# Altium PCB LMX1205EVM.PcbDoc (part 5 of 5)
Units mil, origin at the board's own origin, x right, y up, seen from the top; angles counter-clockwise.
Board outline 5000 x 5000 mil, 6 copper layers (Top Layer, RF GND, Signal Layer 3, Signal Layer 4, Signal Layer 5, Bottom Layer), stack 61.6 mil thick; 176 components, 99 nets, 572 pads, 2473 vias.
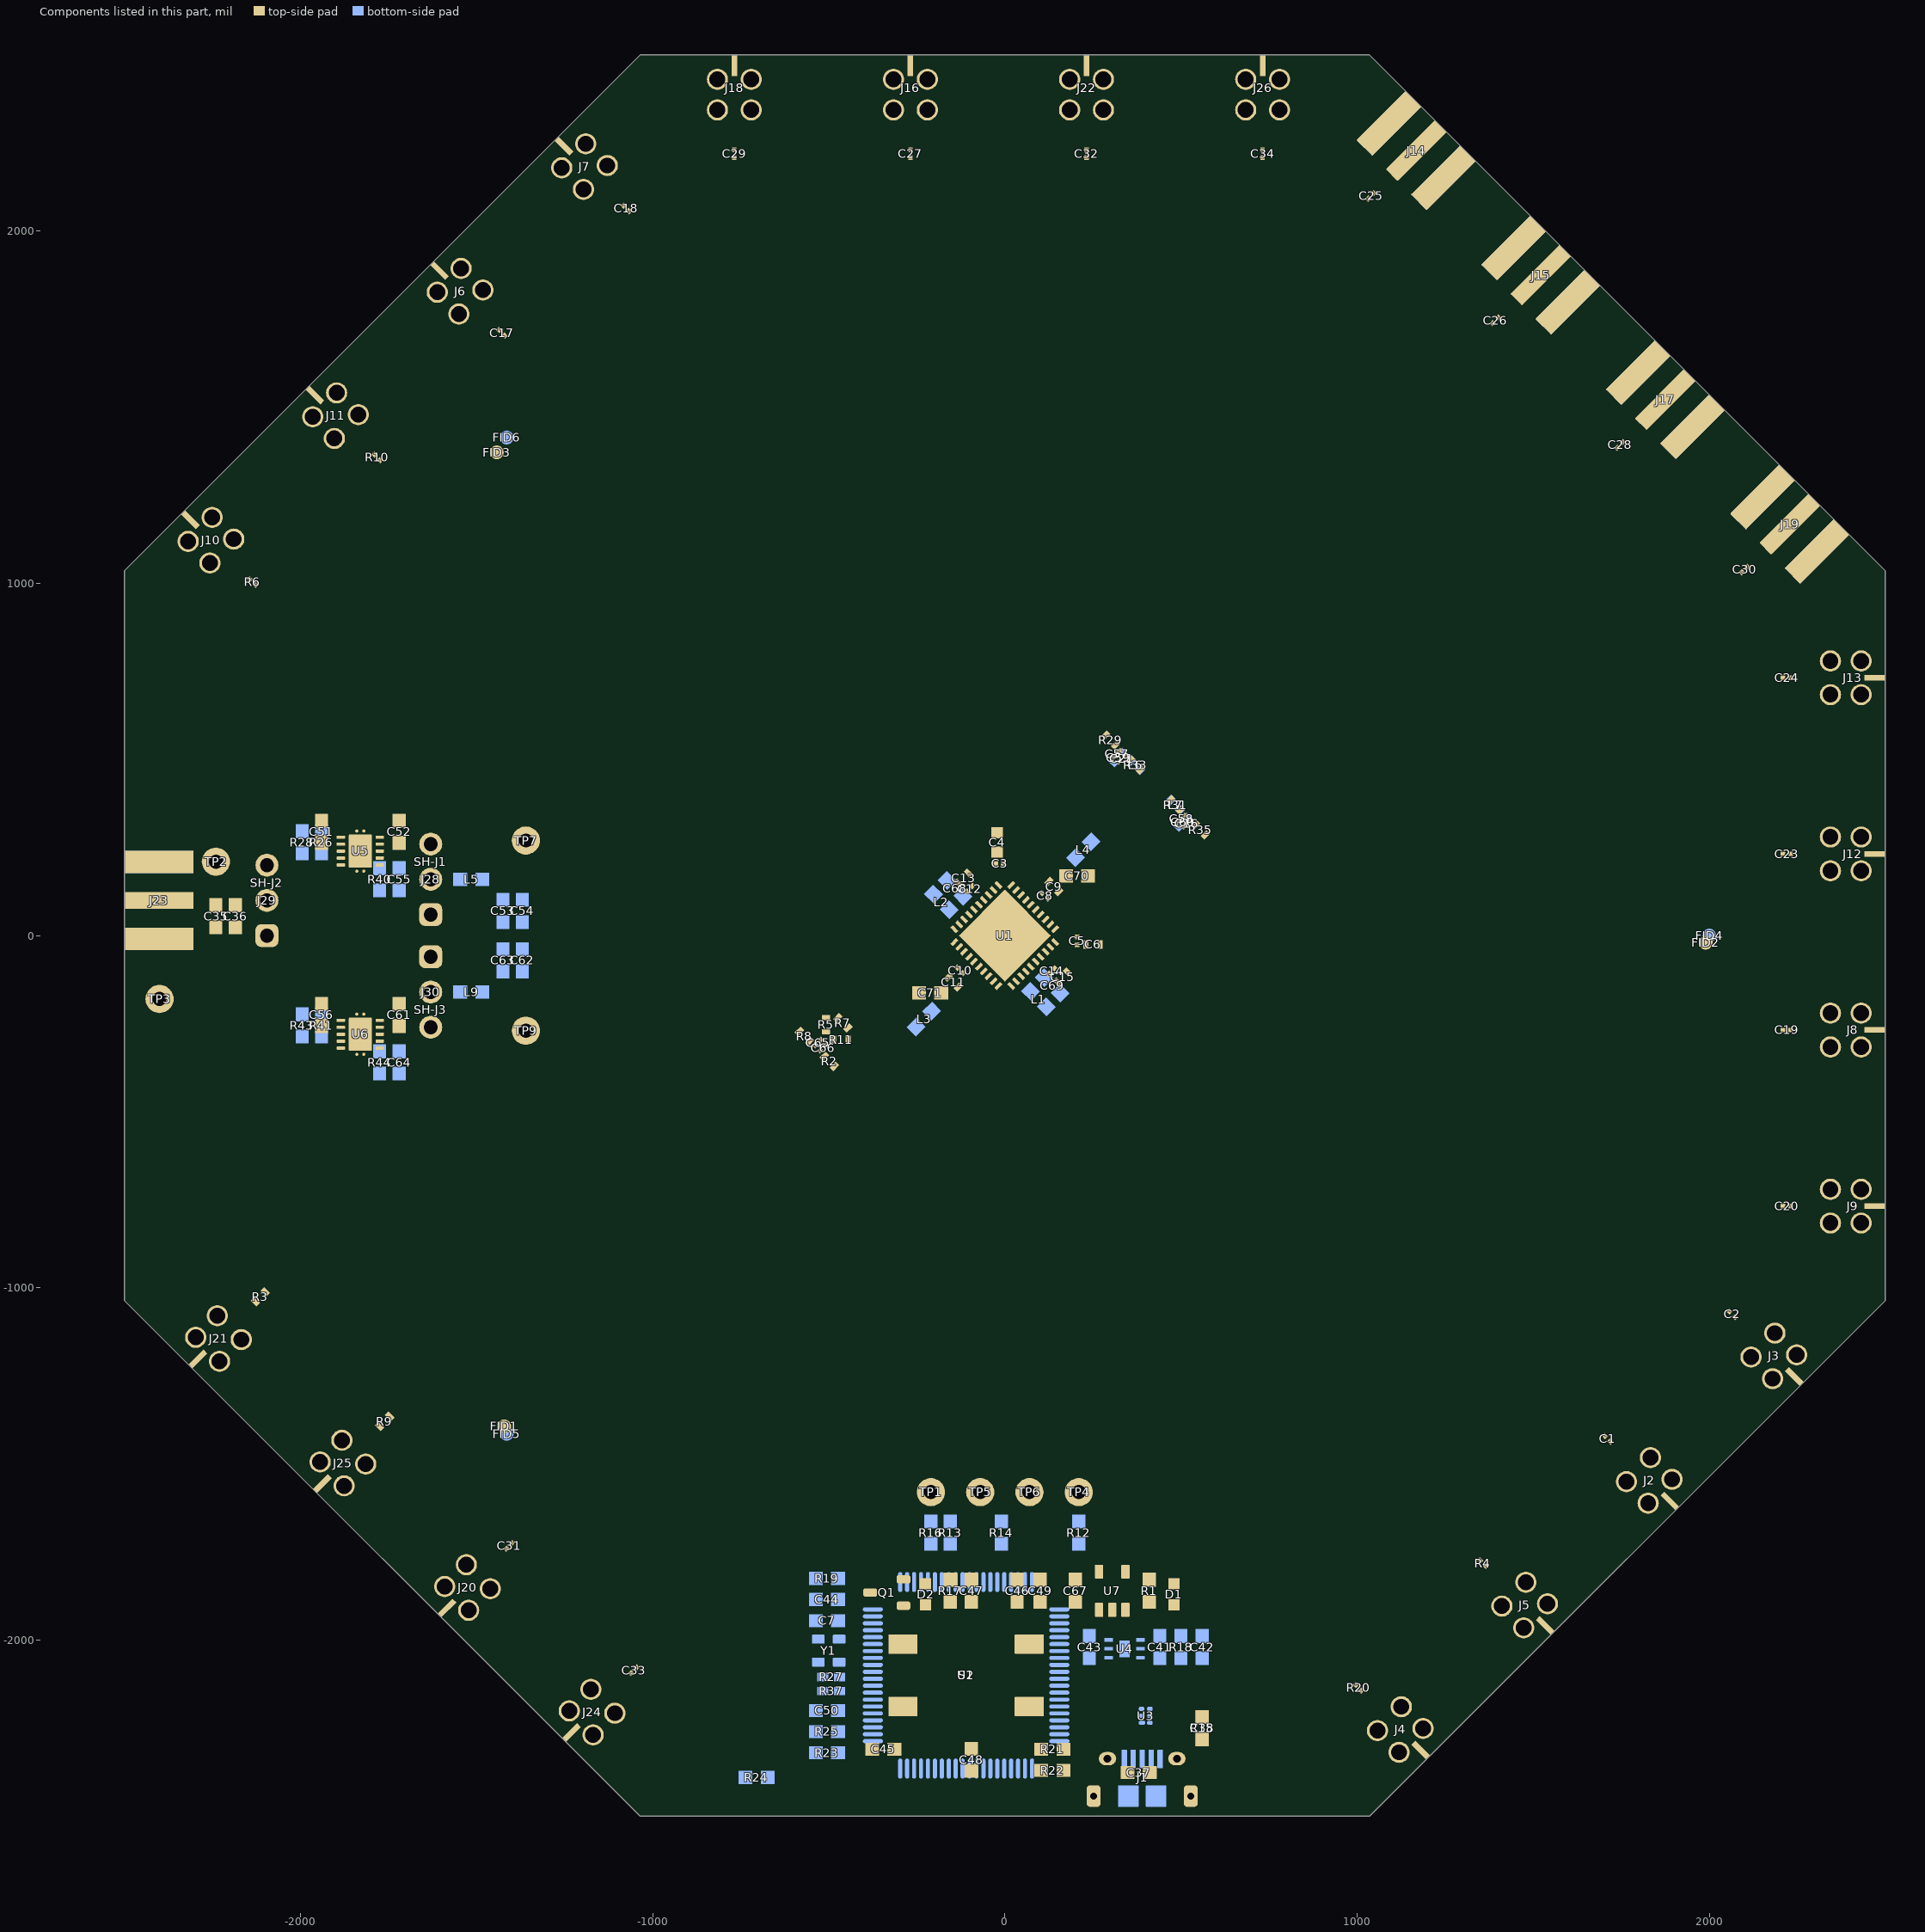
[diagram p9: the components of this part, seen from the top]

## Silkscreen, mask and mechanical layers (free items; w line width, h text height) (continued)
M6 Assembly Bottom:
  lines w10: -3692.5,-4727.33 2909.5,-4727.33 ; -3690.5,-4930.67 2909.5,-4930.67 ; -2284.5,-5140.5 -2284.5,-4937.67 ; -1662.5,-4727.33 -1662.5,-4524 ; -822.5,-4727.33 -822.5,-4524 ; 444.5,-5134 444.5,-4524 ; 1333.5,-5134 2909,-5134 2909,-4524 -3692.5,-4524 -3692.5,-5134 -1095.5,-5134 2909.5,-5134 2909.5,-4524
  text "COMPONENTS MARKED 'DNP' SHOULD NOT BE POPULATED." at 2702,-4318 h60
  text ".VariantName" at 1658,-4434 h60
  text "ASSEMBLY VARIANT:" at 2697,-4434 h60
  text ".VersionControl_RevNumber" at -2364.5,-4656.17 h60
  text "SVN REV:" at -1858.5,-4656.17 h60
  text ".PCB_Rev" at -1312,-4656.17 h60
  text "REV:" at -1020.5,-4656.17 h60
  text ".PRJ_Number" at -176,-4656.17 h60
  text "BOARD #:" at 369.5,-4656.17 h60
  text "PCB VIEWED FROM BOTTOM SIDE" at 2846,-4656.17 h60
  text ".TID" at -176,-4859.5 h60
  text "TID #:" at 369.5,-4859.5 h60
  text ".Layer_Name" at 2040.5,-4870 h60
  text "Layer Name =" at 2825,-4870 h60
  text "TEXAS INSTRUMENTS" at -2495.5,-5064.84 h60
  text ".Print_Time" at -1231,-5064.84 h60
  text ".Print_Date" at -502,-5064.84 h60
  text "GENERATED    :" at 367.5,-5064.84 h60
  text ".plot_File_Name" at 2040.5,-5064.84 h60
  text "PLOT NAME =" at 2846,-5064.84 h60
M7 LPKF Text Top:
  circle w1: c0,0 r380
  pour cut-out: -176.78,-176.78 cw(c0,0) -176.78,176.78 cw(c0,0) 176.78,176.78 cw(c0,0) 176.78,-176.78 cw(c0,0)
  lines w0.5: -2545.58,-989.95 -989.95,-2545.58 ; -2545.58,989.95 -989.95,2545.58 ; -2500,-1100 -2500,1100 ; -1100,-2500 1100,-2500 ; -1100,2500 1100,2500 ; 989.95,-2545.58 2545.58,-989.95 ; 989.95,2545.58 2545.58,989.95 ; 2500,-1100 2500,1100
  lines w1: -2015.25,813.17 -883.88,1944.54 ; -1909.19,-919.24 -951.06,-1877.37 ; -1902.12,940.45 -1887.97,926.31 ; -1884.44,-965.2 -1863.23,-943.99 ; -1781.91,820.24 -898.03,1704.13 ; -1739.48,-862.67 -883.88,-1718.27 ; -1718.27,1124.3 -1704.13,1110.16 ; -1700.59,823.78 -1651.09,774.28 ; -1697.06,-1145.51 -1682.91,-1131.37 ; -1682.91,791.96 -1569.78,905.1 ; -1672.31,-837.92 -1640.49,-806.1 ; -1672.31,-802.57 -1537.96,-936.92 ; -1647.56,869.74 -1552.1,774.28 ; -1622.81,-887.42 -1587.45,-852.06 ; -1601.6,922.77 -1552.1,873.28 ; -1573.31,-936.92 -1541.49,-905.1 ; -1198.55,1651.09 -1173.8,1626.35 ; -1180.87,-1675.84 -1152.58,-1647.56 ; -1131.37,565.69 -707.11,989.95 ; -1035.91,-661.14 -696.5,-1000.56 ; -1011.16,1831.41 -993.49,1813.73 ; -1000.56,1537.96 -936.92,1474.32 ; -997.02,-1859.69 -968.74,-1831.41 ; -982.88,1492 -855.6,1619.27 ; -968.74,-1506.14 -823.78,-1651.09 ; -961.67,-1541.49 -933.38,-1513.21 ; -940.45,1576.85 -901.56,1537.96 ; -911.97,-1590.79 -883.88,-1562.71 ; -901.56,1636.95 -837.92,1573.31 ; -862.67,-1640.49 -834.39,-1612.2 ; -688,2000 657,2000 ; -648,1970 -648,2030 ; -625,1840 -410,1840 ; -618,1750 -418,1750 ; -588,1740 -588,1765 ; -518,1730 -518,1780 ; -509.12,254.56 -403.05,148.49 ; -487.9,190.92 -261.63,417.19 ; -480.83,-197.99 -222.74,-456.08 ; -466.69,-254.56 -392.44,-180.31 ; -466.69,169.71 -240.42,395.98 ; -448,1740 -448,1765 ; -438.41,-155.56 -180.31,-413.66 ; -388,1970 -388,2030 ; -325,-2262.32 -300,-2262.32 ; -324,-2232.64 -300,-2232.64 ; -308,-2268 -308,-2226 ; -296.98,410.12 -219.2,332.34 ; -272.24,-427.8 -208.6,-364.16 ; -263,1200 227,1200 ; -210,430 145,430 ; -210,480 145,480 ; -155,415 -155,505 ; 105,410 105,495 ; 155.56,-480.83 403.05,-233.35 ; 155.56,-410.12 226.27,-480.83 ; 173.24,420.73 427.8,166.17 ; 176.78,-502.05 424.26,-254.56 ; 197.99,381.84 265.16,449.01 ; 215.67,463.15 470.23,208.6 ; 350.02,-236.88 399.52,-286.38 ; 352,1970 352,2040 ; 382,1750 582,1750 ; 385.37,201.53 438.41,254.56 ; 386,1840 575.15,1840 ; 405,-155 510,-155 ; 410,105 505,105 ; 412,1735 412,1765 ; 430,-195 430,140 ; 480,-195 480,150 ; 482,1705 482,1795 ; 552,1735 552,1765 ; 612,1970 612,2040 ; 639.93,-1057.12 979.34,-717.71 ; 657.61,1039.45 1053.59,643.47 ; 777.82,-1697.06 919.24,-1555.63 ; 784.89,-1661.7 813.17,-1689.99 ; 813.17,-1590.99 883.88,-1661.7 ; 813.17,1619.27 862.67,1668.77 ; 820.24,-1781.91 1689.99,-912.17 ; 823.78,1651.09 943.99,1530.89 ; 848.53,1555.63 919.24,1626.35 ; 873.28,1728.88 1021.77,1580.38 ; 883.88,-1562.71 912.17,-1590.99 ; 898.03,-1930.4 1849.08,-979.34 ; 912.17,1520.28 961.67,1569.78 ; 912.17,1916.26 1902.12,926.31 ; 926.31,-1887.97 940.45,-1902.12 ; 940.45,1831.41 989.95,1880.9 ; 1110.16,-1704.13 1124.3,-1718.27 ; 1120.76,1644.02 1173.8,1697.06 ; 1200,-245 1200,235 ; 1484.92,-989.95 1629.88,-844.99 ; 1488.46,-951.06 1523.82,-986.41 ; 1520.28,954.59 1668.77,806.1 ; 1527.35,-890.95 1594.53,-958.13 ; 1527.35,919.24 1555.63,947.52 ; 1555.63,848.53 1626.35,919.24 ; 1587.45,-852.06 1622.81,-887.42 ; 1587.45,1014.7 1725.34,876.81 ; 1619.27,813.17 1661.7,855.6 ; 1629.88,-1177.33 1651.09,-1198.55 ; 1651.09,1127.84 1697.06,1173.8 ; 1720,-518 1775,-518 ; 1720,412 1785,412 ; 1720,482 1785,482 ; 1720,552 1785,552 ; 1730,-588 1775,-588 ; 1730,-448 1775,-448 ; 1750,-618 1750,-418 ; 1750,377 1750,587 ; 1813.73,-993.48 1834.94,-1014.7 ; 1831.41,940.45 1887.98,997.02 ; 1840,-629 1840,-550 ; 1840,384 1840,577 ; 1975,-648 2020,-648 ; 1975,-388 2020,-388 ; 1975,352 2025,352 ; 1975,612 2025,612 ; 2000,-710 2000,675
  lines w10: -2600,0 -1600,0 ; -190,0 0,-190 190,0 0,190 -190,0
M8 LPKF Text Bottom:
  lines w1: -2455,-205 -2345,-205 ; -2425,-770.26 -2370,-770.26 ; -2415,-785 -2415,-765 ; -2415,-230 -2415,-180 ; -2390.47,-860.72 -2355.11,-825.37 ; -2385.07,-847.82 -2376.59,-856.31 ; -2385,-785 -2385,-765 ; -2385,-230 -2385,-180 ; -2364.57,-825.9 -2356.08,-834.39 ; -870.45,-2362.44 -856.31,-2376.59 ; -867.23,-2376.97 -831.88,-2341.62 ; -849.24,-2341.23 -835.09,-2355.37 ; -790,-2405 -765,-2405 ; -790,-2375 -765,-2375 ; -780.26,-2415 -780.26,-2365 ; -766,-2402 -766,-2418.7 -703.19,-2418.7 ; -766,-2381 -766,-2361.3 -703.19,-2361.3
  lines w2: -1500,-270 -1450,-320 ; -1500,270 -1450,320 ; -625.79,-314.66 -187.38,-753.07 -45.96,-753.07 ; -600,-320 -1500,-320 -1500,-80 -400,-80 ; -555.08,88.39 -67.18,-399.52 -53.03,-399.52 109.6,-236.88 70.71,-197.99 ; -500,80 -1500,80 -1500,320 -400,320 ; -473.05,345.78 -201.53,74.25 -169.71,106.07 -98.99,35.36 ; -420.73,-67.18 -60.1,-427.8 427.8,60.1 205.06,282.84 ; -104.65,41.01 -138.59,7.07 -138.59,-7.07 -7.07,-138.59 7.07,-138.59 41.01,-104.65 106.07,-169.71 70.71,-205.06 ; -53.03,-760.14 682.36,-24.75 ; 205.06,304.06 388.91,487.9 ; 212.13,275.77 212.13,311.13 ; 381.84,487.9 491.44,378.3 ; 487.9,388.91 441.94,342.95 441.94,328.8 671.75,98.99 671.75,-42.43
M9 Title Sheet:
  lines w10: -3891.5,-2958.5 -3691.5,-2958.5 ; -3891.5,-583.5 -3691.5,-583.5 ; -3891.5,1791.5 -3691.5,1791.5 ; -1391.5,-5333.5 -1391.5,-5133.5 ; -1391.5,3966.5 -1391.5,4166.5 ; 1108.5,-5333.5 1108.5,-5133.5 ; 1108.5,3966.5 1108.5,4166.5 ; 2921,-5133.5 2921,-4523.5 7903.5,-4523.5 ; 3608.5,-5333.5 3608.5,-5133.5 ; 3608.5,3966.5 3608.5,4166.5 ; 6108.5,-5333.5 6108.5,-5133.5 ; 6108.5,3966.5 6108.5,4166.5 ; 7903.5,-5133.5 7903.5,-4523.5 ; 7903.5,-4823.5 10903.5,-4823.5 ; 7903.5,-4223.5 10903.5,-4223.5 ; 7904.5,-3629.5 10904.5,-3629.5 ; 8608.5,-5333.5 8608.5,-5133.5 ; 8608.5,3966.5 8608.5,4166.5 ; 9408.5,-5123.5 9408.5,-4523.5 ; 10903.5,-4523.5 7903.5,-4523.5 ; 10903.5,-3923.5 7903.5,-3923.5 ; 10908.5,-3933.5 10908.5,-5133.5 ; 10908.5,-3129 7904.5,-3129 7903.5,-3129 7903.5,-3629.5 7903.5,-3923.5 ; 10908.5,-2958.5 11108.5,-2958.5 ; 10908.5,-583.5 11108.5,-583.5 ; 10908.5,1791.5 11108.5,1791.5 ; 7903.5,-4523.5 7903.5,-3923.5 ; 10908.5,-5133.5 10908.5,3966.5 -3691.5,3966.5 -3691.5,-5133.5 10908.5,-5133.5 ; -3891.5,-5333.5 -3891.5,4166.5 11108.5,4166.5 11108.5,-5333.5 -3891.5,-5333.5
  text "1" at -2660.16,4036.5 h70
  text "2" at -164.5,4036.5 h70
  text "3" at 2324.84,4036.5 h70
  text "4" at 4831.51,4036.5 h70
  text "5" at 7330.5,4036.5 h70
  text "6" at 9835.5,4036.5 h70
  text "A" at -3816.5,2893.5 h70
  text "A" at 10983.5,2893.5 h70
  text "B" at -3816.5,513.5 h70
  text "B" at 10983.5,513.5 h70
  text "C" at -3816.5,-1861.5 h70
  text "C" at 10983.5,-1861.5 h70
  text "PROJECT TITLE:" at 7943.5,-3722.5 h45
  text ".PRJ_Title" at 7993.5,-3855.83 h70
  text "DESIGNED FOR:" at 7943.5,-4023.5 h45
  text ".PRJ_Customer" at 7993.5,-4163.5 h70
  text "D" at -3816.5,-4231.5 h70
  text "D" at 10983.5,-4231.5 h70
  text "FILE NAME:" at 7943.5,-4323.5 h45
  text ".PCB_File_Name_No_Path" at 7993.5,-4443.5 h70
  text "Texas Instruments (TI) and/or its licensors do not warrant the accuracy or completeness of this specification" at 2974,-4605.34 h45
  text "ENGINEER:" at 7943.5,-4613.5 h45
  text "LAYOUT BY:" at 9448.5,-4613.5 h45
  text "or any information contained therein. TI and/or its licensors do not warrant that this design will meet" at 2929.01,-4718 h45
  text ".PRJ_Engineer" at 7993.5,-4768.49 h70
  text ".PCB_Layout" at 9499,-4768.49 h70
  text "the specifications, will be suitable for your application or fit for any particular purpose, or will operate in" at 2929.01,-4830.67 h45
  text "ALTIUM DESIGNER VERSION:" at 9448.5,-4923.5 h45
  text "an implementation. TI and/or its licensors do not warrant that the design is production worthy. You should" at 2929.01,-4943.33 h45
  text "completely validate and test your design implementation to confirm the system functionality for your application." at 2974,-5056 h45
  text ".print_Scale" at 7993.5,-5056.83 h70
  text ".Application_BuildNumber" at 9499,-5056.83 h70
  text "1" at -2660.16,-5263.5 h70
  text "2" at -164.5,-5263.5 h70
  text "3" at 2324.84,-5263.5 h70
  text "4" at 4831.51,-5263.5 h70
  text "5" at 7330.5,-5263.5 h70
  text "6" at 9835.5,-5263.5 h70
M10 Fab Notes:
  drawing of 189 lines, arcs and shapes, not listed
  text "DESIGN INFORMATION" at 8982.02,2356.17 h60
  text "MIN. TRACK WIDTH:" at 8337.46,2224.05 h60
  text "MIL" at 9588.46,2224.05 h60
  text "9.5" at 9370,2220 h60
  text "MIN. CLEARANCE:" at 8337.46,2099.92 h60
  text "7.874" at 9275,2100 h60
  text "MIL" at 9588.46,2099.92 h60
  text "19.68" at 9291,1977 h60
  text "MIN. VIA PAD SIZE:" at 8337.46,1975.8 h60
  text "MIL" at 9588.46,1975.8 h60
  text "0.05mm (2MIL)" at 9032.46,1845.9 h60
  text "MINIMUM ANNULAR RING" at 8008.23,1837.67 h60
  text "EXTERNAL" at 9740.46,1837.67 h60
  text "PER" at 8208.23,1727.55 h60
  text "IPC-D-275 CLASS 2 LEVEL C" at 8428.23,1727.54 h60
  text "MIL, HOLES" at 9916.46,1627.07 h60
  text "+/-" at 9524,1618.48 h60
  text "+/-" at 10378,1618.48 h60
  text "REGISTRATION TOLERANCES:" at 8008.23,1617.42 h60
  text "METAL" at 9208,1617.42 h60
  text "5" at 9784.2,1617.42 h60
  text "3" at 10617.2,1617.42 h60
  text "MIL" at 10733.46,1617.42 h60
  text "HOLE SIZE TOLERANCE (UNLESS OTHERWISE SPECIFIED):" at 8008.23,1519.1 h60
  text "+/-" at 10378,1516.23 h60
  text "3" at 10617.2,1515.17 h60
  text "MIL" at 10733.46,1515.17 h60
  text "MATERIAL:" at 7933.46,1377.52 h60
  text "FR-4 High Tg" at 8919.9,1249 h60
  text "X" at 9665,1240 h60
  text "FR-408" at 8354.46,1236.49 h60
  text "OTHER" at 9842.46,1236.49 h60
  text "REFER STACKUP" at 10186,1235 h50
  text "62 MIL (1.6mm) +/-10%" at 8674.56,1093.46 h60
  text "X" at 8554.46,1091.01 h60
  text "THICKNESS:" at 8008.23,1085.24 h60
  text "OTHER" at 9959.46,1085.24 h60
  text "TOLERANCE:" at 8008.23,946.92 h60
  text "X" at 8856.46,946.92 h60
  text "ANSI IPC-6012 TYPE 3 CLASS 2" at 9034.48,946.92 h60
  text "OTHER +/-" at 9034.46,802.73 h60
  text "BOW & TWIST:" at 8008.23,657.54 h60
  text "X" at 8856.46,657.54 h60
  text "ANSI IPC-6012 TYPE 3 CLASS 2" at 9034.48,657.54 h60
  text "OTHER +/-" at 9034.46,510.85 h60
  text "DRILLING:" at 7933.46,380.23 h60
  text "NC_DRILL FILES" at 9694.46,275.04 h60
  text "REFERENCE:" at 8008.23,271.1 h60
  text "X" at 8665.46,271.01 h60
  text "AS SHOWN" at 8843.46,271.1 h60
  text "X" at 9566.46,271.1 h60
  text "OTHER" at 9992.46,128.85 h60
  text "PTH COPPER THICKNESS:" at 8007.91,125.32 h60
  text "X" at 9147.14,125.32 h60
  text "20-30 um" at 9275.14,125.32 h60
  text "BOARD FINISH:" at 7933.46,-22.27 h60
  text "SILKSCREEN:" at 8088.68,-132.4 h60
  text "X" at 9046.46,-132.4 h60
  text "TOP" at 9163.46,-132.4 h60
  text "X" at 9556.46,-132.4 h60
  text "BOTTOM" at 9674.46,-132.4 h60
  text "BLACK" at 10238,-247 h60
  text "SILKSCREEN COLOR:" at 8088.68,-287.59 h60
  text "WHITE" at 9163.46,-287.59 h60
  text "X" at 9556.46,-287.59 h60
  text "OTHER" at 9674.46,-287.59 h60
  text "X" at 9771,-417 h60
  text "GREEN" at 9294.46,-431.04 h60
  text "OTHER" at 9912.46,-431.04 h60
  text "WHITE" at 10463,-435 h60
  text "SOLDER RESIST COLOR:" at 8088.68,-437.9 h60
  text "X" at 9176.46,-585.29 h60
  text "MATTE" at 9294.46,-585.29 h60
  text "SEMI-GLOSS" at 9912,-585.93 h60
  text "IMMERSION GOLD (ENIG)" at 8994.46,-758.06 h60
  text "ENEPIG" at 10332,-765.28 h60
  text "SURFACE FINISH:" at 7933.46,-766.28 h60
  text "X" at 8816.46,-766.28 h60
  text "IMM. TIN/SILVER OR EQUIV" at 8263,-903.6 h60
  text "OTHER" at 9694.46,-907.53 h60
  text "X" at 8806,-1060 h60
  text "ARRAY/PANEL:" at 7933.46,-1062.91 h60
  text "CUT AND TRIM PER M1 BOARD OUTLINE" at 8994.46,-1071.13 h60
  text "NOTE:" at 3400,-1200 h60
  text "N.C. ROUTE" at 8994.46,-1207.1 h60
  text "V. SCORE" at 9860.46,-1207.1 h60
  text "CERTIFICATION:" at 7933.46,-1336.23 h60
  text "MATERIALS AND WORKMANSHIP FOR ALL PCBS" at 8658.46,-1336.23 h60
  text "1)  ALL 16 MIL TRACE WIDTH HAVING 50 OHM IMPEDANCE IN TOP LAYER WITH +/- 10% TOLERANCE." at 3400,-1350 h55
  text "TO MEET OR EXCEED THE REQUIREMENTS OF:" at 8658.46,-1430.29 h60
  text "2)  ALL VIAS ARE TENTED, UNLESS OTHERWISE MASK IS OPENED IN GERBERS" at 3400,-1450 h55
  text "3)  VENDOR MAY ADJUST SOLDERMASK WHEREVER SOLDERMASK PADS ARE THE SAME SIZE(1:1)" at 3400,-1550 h55
  text "X" at 8295.97,-1558.92 h60
  text "ANSI IPC-A-600F CLASS ->" at 8423.96,-1558.92 h60
  text "X" at 10071.97,-1558.92 h60
  text "2" at 10181.96,-1558.92 h60
  text "1" at 9866.96,-1560.42 h60
  text "3" at 10535.96,-1560.42 h60
  text "AS PER THE MANUFACTURING CAPABILITIES AND ALL OTHER SOLDER MASK PADS SHALL NOT BE MODIFIED." at 3557,-1650 h55
  text "X" at 9107.97,-1706.61 h60
  text "RoHS" at 9235.96,-1706.61 h60
  text "OTHER" at 9880.36,-1706.61 h60
  text "PER ORDER" at 10277.42,-1706.61 h60
  text "PROVIDED NO ADJACENT COPPER IS EXPOSED AND NO CONFLICT IS PRODUCED WITH ANY STATED" at 3557,-1750 h55
  text "\"VIA TENTING/COVERING\" REQUIREMENTS." at 3557,-1850 h55
  text "ALL BOARDS MUST MEET OR EXCEED UL94-V0 REQUIREMENTS." at 7961,-1860.43 h60
  text "PCB MUST BEAR THE UL94V-0 UL REGISTERED MATERIAL ID NUMBER" at 7961,-1976.5 h60
  text "ADDITIONAL REQUIREMENTS:" at 7933.46,-2145.92 h60
  text "MICROSECTION:" at 8008.23,-2253.05 h60
  text "YES" at 8913.96,-2253.05 h60
  text "REQUIRED" at 9775.46,-2397.38 h60
  text "BARE BOARD ELEC. TEST:" at 8008.23,-2400.24 h60
  text "NONE" at 9313.96,-2400.24 h60
  text "X" at 9657.46,-2400.24 h60
  text "PER ORDER" at 10367.46,-2400.24 h60
  text "XX MIL VIAS REQUIRE NON-CONDUCTIVE FILL AND PLANARIZE" at 8176.38,-2605.18 h59
  text "XX MIL VIAS REQUIRE CONDUCTIVE FILL AND PLANARIZE" at 8184.38,-2709.16 h60
  text "OUTER XX MIL TRACES REQUIRE 50 OHM SINGLE-ENDED IMPEDANCE" at 8183.39,-2872.54 h58
  text "LAYER 2 & 3 (INNER LAYERS) XX MIL WIDE, XX MIL SPACE / TRACES REQUIRE 100 OHM DIFFERENTIAL IMPEDANCE" at 8175.39,-3108.26 h60
M11 Gerber Information:
  lines w10: -3692,-4930.17 2908,-4930.17 ; -3692,-4726.83 2910,-4726.83 ; -3692,-4523.5 -3692,-5133.5 313,-5133.5 2910,-5133.5 2910,-4523.5 -3691.5,-4523.5 -3691.5,-5133.5 -2116,-5133.5 ; -1227,-5133.5 -1227,-4523.5 ; 40,-4726.83 40,-4523.5 ; 880,-4726.83 880,-4523.5 ; 1502,-5140 1502,-4937.17
  text "ALL ARTWORK VIEWED FROM TOP SIDE" at -3628.5,-4655.67 h60
  text "BOARD #:" at -1152,-4655.67 h60
  text ".PRJ_Number" at -606.5,-4655.67 h60
  text "REV:" at 238,-4655.67 h60
  text ".PCB_Rev" at 529.5,-4655.67 h60
  text "SVN REV:" at 1076,-4655.67 h60
  text ".VersionControl_RevNumber" at 1582,-4655.67 h60
  text "LAYER NAME =" at -3628.5,-4858.49 h60
  text "TID #:" at -1152,-4859 h60
  text ".TID" at -606.5,-4859 h60
  text "PLOT NAME =" at -3628.5,-5064.34 h60
  text ".plot_File_Name" at -2823,-5064.34 h60
  text "GENERATED    :" at -1150,-5064.34 h60
  text ".Print_Date" at -280.5,-5064.34 h60
  text ".Print_Time" at 448.5,-5064.34 h60
M12 Stackup:
  drawing of 399 lines, arcs and shapes, not listed
  text "Layer" at 3135.34,1018 h60
  text "Name" at 3545.26,1018 h60
  text "Material" at 4485,1018 h60
  text "Thickness" at 5344.76,1018 h60
  text "Constant" at 5994.6,1018 h60
  text "Board Layer Stack" at 6564.46,1018 h60
  text "1" at 3135.34,898 h60
  text "Top Overlay" at 3545.26,898 h60
  text "2" at 3135.34,778 h60
  text "Top Solder" at 3545.26,778 h60
  text "Solder Resist" at 4485,778 h60
  text "0.40mil" at 5344.76,778 h60
  text "3.5" at 5994.6,778 h60
  text "3" at 3135.34,658 h60
  text "Top Layer" at 3545.26,658 h60
  text "Copper" at 4485,658 h60
  text "2.80mil" at 5344.76,658 h60
  text "4" at 3135.34,538 h60
  text "Dielectric1" at 3545.26,538 h60
  text "RO4350B" at 4485,538 h60
  text "8.00mil" at 5344.76,538 h60
  text "3.48" at 5994.6,538 h60
  text "5" at 3135.34,418 h60
  text "RF GND" at 3545.26,418 h60
  text "Copper" at 4485,418 h60
  text "1.40mil" at 5344.76,418 h60
  text "6" at 3135.34,298 h60
  text "Dielectric 2" at 3545.26,298 h60
  text "FR-4 High Tg" at 4485,298 h60
  text "11.00mil" at 5344.76,298 h60
  text "4.2" at 5994.6,298 h60
  text "7" at 3135.34,178 h60
  text "Signal Layer 3" at 3545.26,178 h60
  text "Copper" at 4485,178 h60
  text "1.40mil" at 5344.76,178 h60
  text "8" at 3135.34,58 h60
  text "Dielectric 3" at 3545.26,58 h60
  text "FR-4 High Tg" at 4485,58 h60
  text "12.40mil" at 5344.76,58 h60
  text "4.2" at 5994.6,58 h60
  text "9" at 3135.34,-62 h60
  text "Signal Layer 4" at 3545.26,-62 h60
  text "Copper" at 4485,-62 h60
  text "1.40mil" at 5344.76,-62 h60
  text "10" at 3135.34,-182 h60
  text "Dielectric 4" at 3545.26,-182 h60
  text "FR-4 High Tg" at 4485,-182 h60
  text "11.00mil" at 5344.76,-182 h60
  text "4.2" at 5994.6,-182 h60
  text "11" at 3135.34,-302 h60
  text "Signal Layer 5" at 3545.26,-302 h60
  text "Copper" at 4485,-302 h60
  text "1.40mil" at 5344.76,-302 h60
  text "12" at 3135.34,-422 h60
  text "Dielectric 5" at 3545.26,-422 h60
  text "FR-4 High Tg" at 4485,-422 h60
  text "8.00mil" at 5344.76,-422 h60
  text "4.2" at 5994.6,-422 h60
  text "13" at 3135.34,-542 h60
  text "Bottom Layer" at 3545.26,-542 h60
  text "Copper" at 4485,-542 h60
  text "2.80mil" at 5344.76,-542 h60
  text "14" at 3135.34,-662 h60
  text "Bottom Solder" at 3545.26,-662 h60
  text "Solder Resist" at 4485,-662 h60
  text "0.40mil" at 5344.76,-662 h60
  text "3.5" at 5994.6,-662 h60
  text "15" at 3135.34,-782 h60
  text "Bottom Overlay" at 3545.26,-782 h60
M13 Component Bodies Top:
  text ".Layer_Name" at -2823,-4858.49 h60
M14 Component Bodies Bottom:
  text ".Layer_Name" at -2823,-4858.49 h60
M15 Courtyards Top:
  text ".Layer_Name" at -2823,-4858.49 h60
M16 Courtyards Bottom:
  text ".Layer_Name" at -2823,-4858.49 h60
Drill Drawing:
  circle w10: c3085.62,3344.23 r27.78
  lines w10: 3057.85,2872.01 3113.4,2872.01 3085.62,2816.45 3057.85,2872.01 ; 3057.85,2955.34 3071.74,2955.34 3071.74,2941.45 3099.51,2941.45 3099.51,2955.34 3113.4,2955.34 3113.4,2983.12 3099.51,2983.12 3099.51,2997.01 3071.74,2997.01 3071.74,2983.12 3057.85,2983.12 3057.85,2955.34 ; 3057.85,3066.45 3113.4,3066.45 3113.4,3122.01 3057.85,3122.01 3057.85,3066.45 ; 3057.85,3219.23 3085.62,3191.45 3113.4,3219.23 3085.62,3247.01 3057.85,3219.23 ; 3057.85,3441.45 3057.85,3455.34 3071.74,3469.23 3057.85,3483.12 3057.85,3497.01 3071.74,3497.01 3085.62,3483.12 3099.51,3497.01 3113.4,3497.01 3113.4,3483.12 3099.51,3469.23 3113.4,3455.34 3113.4,3441.45 3099.51,3441.45 3085.62,3455.34 3071.74,3441.45 3057.85,3441.45 ; 3057.85,3566.45 3113.4,3566.45 3113.4,3622.01 3057.85,3622.01 3057.85,3566.45 ; 3057.85,3691.45 3085.62,3705.34 3113.4,3691.45 3099.51,3719.23 3113.4,3747.01 3085.62,3733.12 3057.85,3747.01 3071.74,3719.23 3057.85,3691.45 ; 3068.96,3577.56 3102.29,3577.56 3102.29,3610.9 3068.96,3610.9 3068.96,3577.56
  lines w15: 3007.5,2778.95 9873.93,2778.95 ; 3007.5,3778.95 9873.93,3778.95 ; 3471.9,2653.95 3471.9,3903.95 ; 4025.08,2653.95 4025.08,3903.95 ; 4986.47,2653.95 4986.47,3903.95 ; 5413.36,2653.95 5413.36,3903.95 ; 6030.2,2653.95 6030.2,3903.95 ; 7283.16,2653.95 7283.16,3903.95 ; 7780.03,2653.95 7780.03,3903.95 ; 8699.76,2653.95 8699.76,3903.95 ; 3007.5,2653.95 9873.93,2653.95 9873.93,3903.95 3007.5,3903.95 3007.5,2653.95
  text "Symbol" at 3082.5,3816.45 h60
  text "Count" at 3509.4,3816.45 h60
  text "Hole Size" at 4062.58,3816.45 h60
  text "Plated" at 5023.97,3816.45 h60
  text "Hole Type" at 5450.86,3816.45 h60
  text "Drill Layer Pair" at 6067.7,3816.45 h60
  text "Via/Pad" at 7320.66,3816.45 h60
  text "Hole Length" at 7817.53,3816.45 h60
  text "Routed Path Length" at 8737.26,3816.45 h60
  text "29" at 3509.4,3691.45 h50
  text "7.87mil (0.200mm)" at 4062.58,3691.45 h50
  text "PTH" at 5023.97,3691.45 h50
  text "Round" at 5450.86,3691.45 h50
  text "Top Layer - Bottom Layer" at 6067.7,3691.45 h50
  text "Via" at 7320.66,3691.45 h50
  text "-" at 7817.53,3691.45 h50
  text "-" at 8737.26,3691.45 h50
  text "2323" at 3509.4,3566.45 h50
  text "12.00mil (0.305mm)" at 4062.58,3566.45 h50
  text "PTH" at 5023.97,3566.45 h50
  text "Round" at 5450.86,3566.45 h50
  text "Top Layer - Bottom Layer" at 6067.7,3566.45 h50
  text "Via" at 7320.66,3566.45 h50
  text "-" at 7817.53,3566.45 h50
  text "-" at 8737.26,3566.45 h50
  text "120" at 3509.4,3441.45 h50
  text "16.00mil (0.406mm)" at 4062.58,3441.45 h50
  text "PTH" at 5023.97,3441.45 h50
  text "Round" at 5450.86,3441.45 h50
  text "Top Layer - Bottom Layer" at 6067.7,3441.45 h50
  text "Via" at 7320.66,3441.45 h50
  text "-" at 7817.53,3441.45 h50
  text "-" at 8737.26,3441.45 h50
  text "2" at 3509.4,3316.45 h50
  text "19.69mil (0.500mm)" at 4062.58,3316.45 h50
  text "PTH" at 5023.97,3316.45 h50
  text "Slot" at 5450.86,3316.45 h50
  text "Top Layer - Bottom Layer" at 6067.7,3316.45 h50
  text "Pad" at 7320.66,3316.45 h50
  text "45.28mil (1.150mm)" at 7817.53,3316.45 h50
  text "25.59mil (0.650mm)" at 8737.26,3316.45 h50
  text "2" at 3509.4,3191.45 h50
  text "21.65mil (0.550mm)" at 4062.58,3191.45 h50
  text "PTH" at 5023.97,3191.45 h50
  text "Slot" at 5450.86,3191.45 h50
  text "Top Layer - Bottom Layer" at 6067.7,3191.45 h50
  text "Pad" at 7320.66,3191.45 h50
  text "33.47mil (0.850mm)" at 7817.53,3191.45 h50
  text "11.81mil (0.300mm)" at 8737.26,3191.45 h50
  text "17" at 3509.4,3066.45 h50
  text "40.00mil (1.016mm)" at 4062.58,3066.45 h50
  text "PTH" at 5023.97,3066.45 h50
  text "Round" at 5450.86,3066.45 h50
  text "Top Layer - Bottom Layer" at 6067.7,3066.45 h50
  text "Pad" at 7320.66,3066.45 h50
  text "-" at 7817.53,3066.45 h50
  text "-" at 8737.26,3066.45 h50
  text "80" at 3509.4,2941.45 h50
  text "45.00mil (1.143mm)" at 4062.58,2941.45 h50
  text "PTH" at 5023.97,2941.45 h50
  text "Round" at 5450.86,2941.45 h50
  text "Top Layer - Bottom Layer" at 6067.7,2941.45 h50
  text "Pad" at 7320.66,2941.45 h50
  text "-" at 7817.53,2941.45 h50
  text "-" at 8737.26,2941.45 h50
  text "1" at 3509.4,2816.45 h50
  text "157.48mil (4.000mm)" at 4062.58,2816.45 h50
  text "PTH" at 5023.97,2816.45 h50
  text "Round" at 5450.86,2816.45 h50
  text "Top Layer - Bottom Layer" at 6067.7,2816.45 h50
  text "Via" at 7320.66,2816.45 h50
  text "-" at 7817.53,2816.45 h50
  text "-" at 8737.26,2816.45 h50
  text "2574 Total" at 3509.4,2691.45 h50
  text "Slot definitions :" at 3082.5,2567.31 h50
  text "Routed Path Length" at 3947.74,2567.31 h50
  text "= Calculated from tool start centre position to tool end centre position." at 4871.3,2567.31 h50
  text "Hole Length" at 3947.74,2480.66 h50
  text "= Routed Path Length + Tool Size = Slot length as defined in the PCB layout" at 4529.74,2480.66 h50
  text ".Layer_Name" at -2823,-4858.49 h60
M17 Embedded Cavity:
  text ".Layer_Name" at -2823,-4858.49 h60
M18 Embedded Assembly:
  text ".Layer_Name" at -2823,-4858.49 h60
M19 Embedded Keepout:
  text ".Layer_Name" at -2823,-4858.49 h60

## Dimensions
-2500,-1300 to 2500,-1300 on M2 Board Dimensions
-1300,2500 to -1300,-2500 on M2 Board Dimensions
-3400,-4400 to -2400,-4400 on M2 Board Dimensions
